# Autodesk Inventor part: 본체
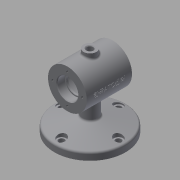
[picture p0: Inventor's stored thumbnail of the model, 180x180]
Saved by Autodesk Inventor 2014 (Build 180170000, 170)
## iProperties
Created: 2018-12
Part Number: 본체
Material: Generic
Document SubType Name: Modeling
Designer: kh
Density: 1 g/cm^3
Appearance: Default
Author: kh
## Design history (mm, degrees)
sketch "Sketch1"
  geometry: L1 (0, 0)-(70, 0); L2 (70, 0)-(70, 30); L3 (70, 30)-(0, 30); L4 (0, 30)-(0, 0)
  constraints: 8 end point, 2 parallel, 1 horizontal, 1 perpendicular
  dimensions: "d0" = 70 distance of L2.end L3.end; "d1" = 60 diameter of L3 L1
revolve "Revolution1" sketch "Sketch1" stored, may be unused: angle "d2" = 90 deg
sketch "Sketch2"
  geometry: L1 (0, -30)-(0, 30) reference; L2 (70, -30)-(70, 30) reference; L3 (0, 30)-(70, 30) reference; L4 (0, -30)-(70, -30) reference; L5 (0, 0)-(70, 0); L6 (0, 17)-(1, 16); L7 (1, 16)-(11.7, 16); L8 (12, 15.7)-(12, 14); L9 (12, 14)-(15, 14); L10 (15, 14)-(15, 22); L11 (18, 25)-(52, 25); L12 (55, 22)-(55, 14); L13 (55, 14)-(58, 14); L14 (58, 14)-(58, 16); L15 (58, 16)-(69, 16); L16 (69, 16)-(70, 17); L17 (0, 17)-(0, 0); L18 (70, 17)-(70, 0); A1 r 3 centre (18, 22) between (18, 25) and (15, 22); A2 r 3 centre (52, 22) between (55, 22) and (52, 25); A3 r 0.3 centre (11.7, 15.7) between (12, 15.7) and (11.7, 16); 2 further points
  constraints: 28 end point, 10 perpendicular, 6 point on circle, 6 point on line, 6 tangent, 3 centre point, 2 collinear, 1 equal radius, 1 midpoint, 1 parallel
  dimensions: "d4" = 50 diameter of L11 L5; "d5" = 28 diameter of L13 L5; "d6" = 28 diameter of L9 L5; "d7" = 32 diameter of L7 L5; "d8" = 32 diameter of L15 L5; "d9" = 1 horizontal distance of L6.start L6.end; "d10" = 1 horizontal distance of L6.start L6.end; "d11" = 1 horizontal distance of L15.end L16.end; "d12" = 12 distance from line of L8 L6.start; "d13" = 12 distance from line of L16.end L14; "d15" = 40 distance of point (15, 25) point (55, 25); "d16" = 3 radius of A1; "d17" = 0.3 radius of A3
revolve "Revolution2" sketch "Sketch2" stored, may be unused: angle "d18" = 90 deg
sketch "Sketch3"
  geometry: L1 (-23, 0)-(23, 0); L2 (0, 23)-(0, -23); C1 r 30 at (0, 0) reference; A1 r 23 centre (0, 0) between (-23, 0) and (23, 0); 3 further points
  constraints: 4 end point, 4 point on circle, 2 coincident, 2 midpoint, 1 centre point, 1 horizontal, 1 perpendicular
  dimensions: "d19" = 46 diameter of A1
hole "Hole1" sketch "Sketch3" at (0, 23) diameter "d20" = 3.242; stored, may be unused: countersink angle "d24" = 90 deg, drill point angle "d26" = 118 deg; dims "d21" = 8, "d22" = 4, "d23" = 2, "d25" = 10
pattern_circular "Circular Pattern1" dims angle "d28" = 360 deg
workplane "Work Plane1"
mirror "Mirror1"
workplane "Work Plane2"
sketch "Sketch4"
  geometry: L1 (0, 30)-(0, -30) reference; L2 (0, -30)-(-70, -30) reference; L3 (-70, 30)-(-70, -30) reference; L4 (0, 30)-(-70, 30) reference; L5 (0, 0)-(-70, 0); L6 (-35, -30)-(-35, 30); C1 r 55 at (-35, 0)
  constraints: 4 end point, 4 midpoint, 1 centre point
  dimensions: "d31" = 110 diameter of C1
extrude "Extrusion1" join sketch "Sketch4" distance "d32" = 11; taper "d33" = 0 deg
sketch "Sketch5"
  geometry: L1 (20, -64)-(-90, -64) reference; L2 (-90, -75)-(-90, -64) reference; L3 (-90, -64)-(-35, -49.263); L4 (0, -30)-(-70, -30) reference; L5 (-35, -64)-(-35, -30); L6 (-35, -49.263)-(-35, -64); L7 (-90, -64)-(-35, -64); 1 further point
  constraints: 8 end point, 2 collinear, 2 midpoint, 1 point on line
  dimensions: "d34" = 75 deg angle of L3 L2
revolve "Revolution3" sketch "Sketch5" stored, may be unused: angle "d35" = 90 deg
sketch "Sketch7"
  geometry: L1 (-90, 0)-(20, 0); L2 (-35, 55)-(-35, -55); C1 r 12 at (-35, 0); A1 r 55 centre (-35, 0) between (-90, 0) and (-35, 55) reference; 2 further points
  constraints: 4 end point, 3 midpoint, 3 point on circle, 1 centre point, 1 coincident, 1 horizontal, 1 perpendicular
  dimensions: "d36" = 24 diameter of C1
extrude "Extrusion2" join sketch "Sketch7" stored distance "d37" = 11; taper "d38" = 0 deg
workplane "Work Plane3"
sketch "Sketch8"
  geometry: L1 (0, -30)-(0, 30) reference; L2 (70, -30)-(70, 30) reference; L3 (0, 0)-(70, 0); L4 (0, 30)-(70, 30) reference; L5 (0, -30)-(70, -30) reference; L6 (35, 30)-(35, -30); C1 r 10 at (35, 0)
  constraints: 4 end point, 4 midpoint, 1 centre point
  dimensions: "d40" = 20 diameter of C1
extrude "Extrusion3" join sketch "Sketch8" stored distance "d41" = 11; taper "d42" = 0 deg
hole "Hole2" diameter "d45" = 10; stored, may be unused: countersink angle "d49" = 90 deg, drill point angle "d51" = 118 deg; dims "d46" = 8, "d47" = 4, "d48" = 2, "d50" = 10, "d52" = 10, "d53" = 10
sketch "Sketch11"
  geometry: L1 (-44, 0)-(44, 0); L2 (0, 44)-(0, -44); C1 r 55 at (0, 0) reference; C2 r 4.5 at (0, 44); C3 r 4.5 at (44, 0); C4 r 4.5 at (0, -44); C5 r 4.5 at (-44, 0); A1 r 44 centre (0, 0) between (-44, 0) and (44, 0); 1 further point
  constraints: 5 centre point, 5 coincident, 4 end point, 4 point on circle, 2 midpoint, 1 horizontal, 1 perpendicular
  dimensions: "d57" = 88 diameter of A1; "d82" = 9 diameter of C2; "d83" = 9 diameter of C3; "d84" = 9 diameter of C4; "d85" = 9 diameter of C5
workplane "Work Plane5"
workplane "Work Plane6"
sketch "Sketch13"
  geometry: L1 (0, -30)-(0, 30) reference; L2 (0, 30)-(70, 30) reference; L3 (10.113, 3.602)-(59.887, 3.602); L4 (59.887, 3.602)-(59.887, -3.602); L5 (59.887, -3.602)-(10.113, -3.602); L6 (10.113, -3.602)-(10.113, 3.602); L7 (10.113, 0)-(59.887, 0); L8 (35, 3.602)-(35, -3.602); 1 further point
  constraints: 4 end point, 4 midpoint, 2 other
  dimensions: "d74" = 35 distance between parallel lines of L8 L1; "d75" = 30 distance between parallel lines of L7 L2
emboss "Emboss1" sketch "Sketch13" dims "d0" = 70, "d1" = 60, "d76" = 0.5, "d77" = 0
fillet "Fillet1" dims "d78" = 3
chamfer "Chamfer1" distance "d79" = 1; stored, may be unused: second distance "d80" = 2, angle "d81" = 45 deg
extrude "Extrusion4" cut sketch "Sketch11" distance "d86" = 10; taper "d87" = 0 deg
sketch "Sketch14"
  geometry: 1 further point
sketch "Sketch15"
  geometry: L1 (-52.776, 0)-(52.776, 0); L2 (-44, 0)-(44, 0); L3 (0, 44)-(0, -44); C1 r 14.224 at (0, 0) reference; C2 r 7 at (0, 44); C3 r 7 at (44, 0); C4 r 7 at (0, -44); C5 r 7 at (-44, 0); A1 r 52.776 centre (0, 0) between (-52.776, 0) and (52.776, 0) reference; A2 r 44 centre (0, 0) between (-44, 0) and (44, 0); 3 further points
  constraints: 6 coincident, 6 end point, 6 point on circle, 5 centre point, 3 midpoint, 2 point on line, 1 horizontal, 1 perpendicular
  dimensions: "d88" = 88 diameter of A2; "d89" = 14 diameter of C2; "d90" = 14 diameter of C3; "d91" = 14 diameter of C4; "d92" = 14 diameter of C5
extrude "Extrusion5" cut sketch "Sketch15" distance "d93" = 10; taper "d94" = 0 deg
body "Solid1"
node "Projected Loop1"
node "Projected Loop6"
other parameters: "d30" = -75, "d39" = 37, "d73" = -59.5
